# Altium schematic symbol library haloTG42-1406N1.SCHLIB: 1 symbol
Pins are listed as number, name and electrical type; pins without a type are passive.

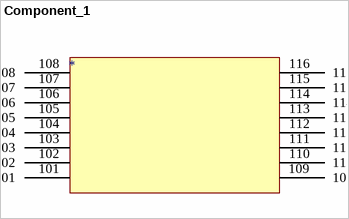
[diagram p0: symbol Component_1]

## Component_1
designator *
pins: 101, 102, 103, 104, 105, 106, 107, 108, 109, 110, 111, 112, 113, 114, 115, 116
